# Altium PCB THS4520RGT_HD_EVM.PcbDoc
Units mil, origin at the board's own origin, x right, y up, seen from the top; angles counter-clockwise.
Board outline 1879 x 3030 mil, 4 copper layers (Top Layer L1, MidLayer L2 (GND), MidLayer L3 (Power), Bottom Layer L4), stack 61.2 mil thick; 48 components, 25 nets, 139 pads, 272 vias.
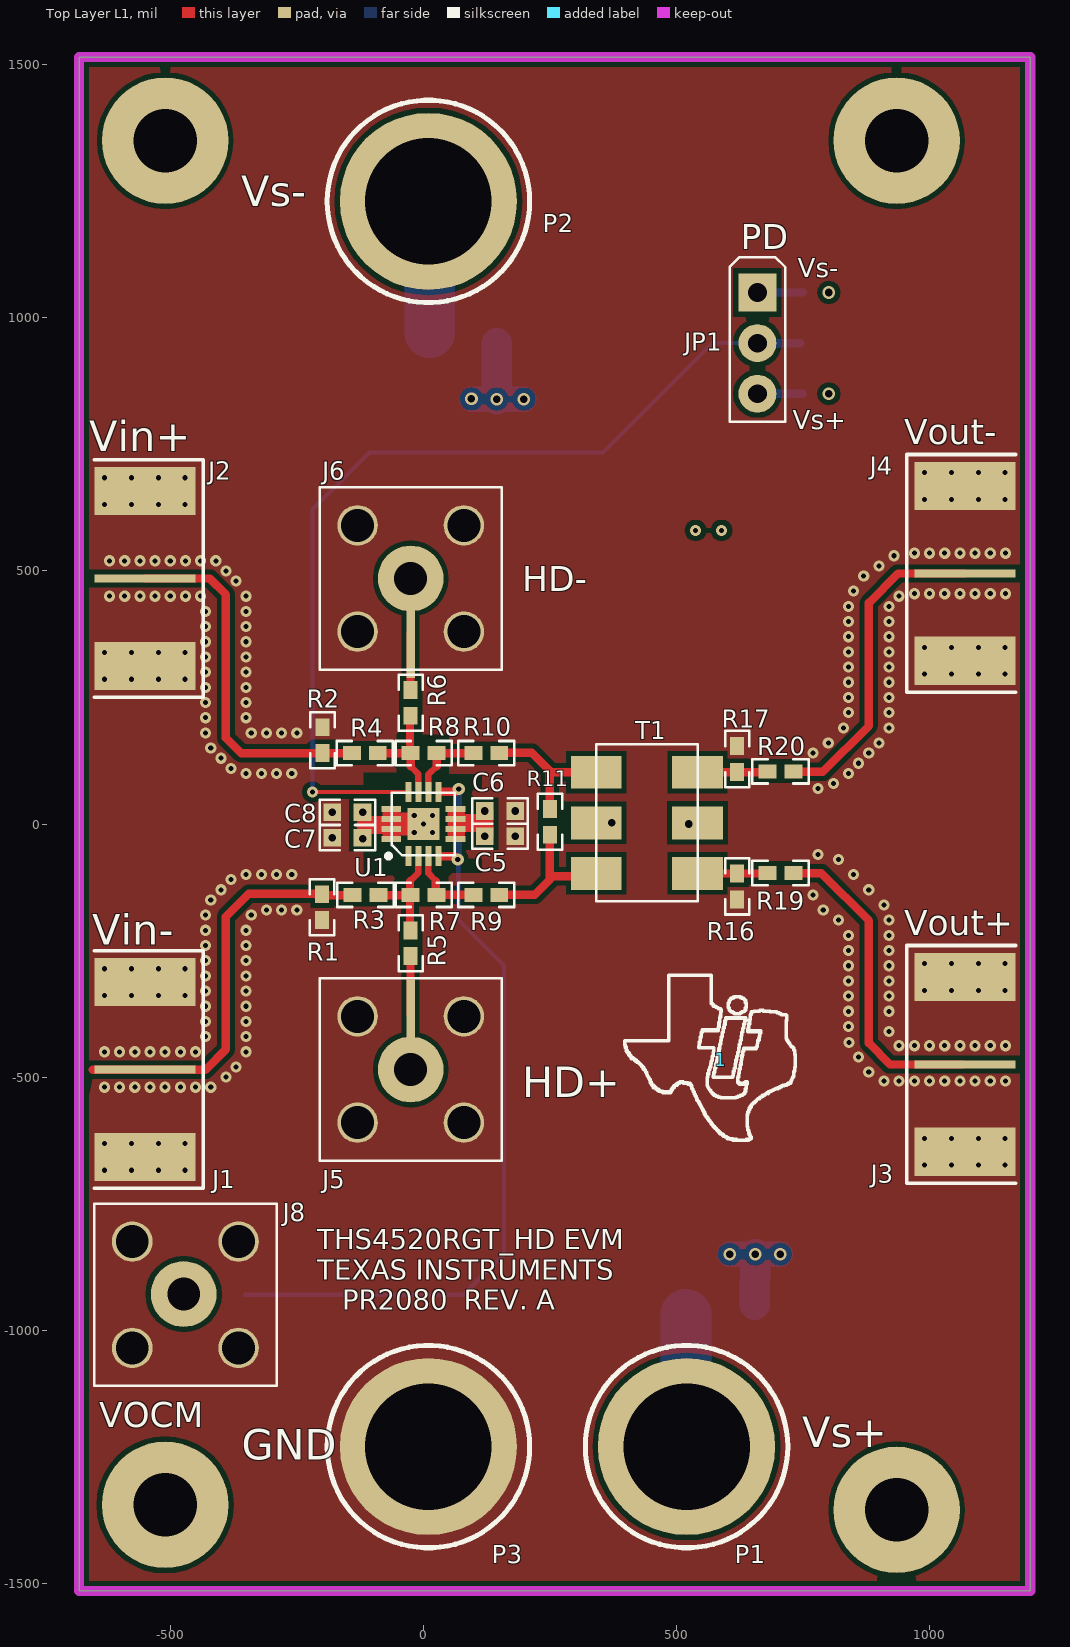
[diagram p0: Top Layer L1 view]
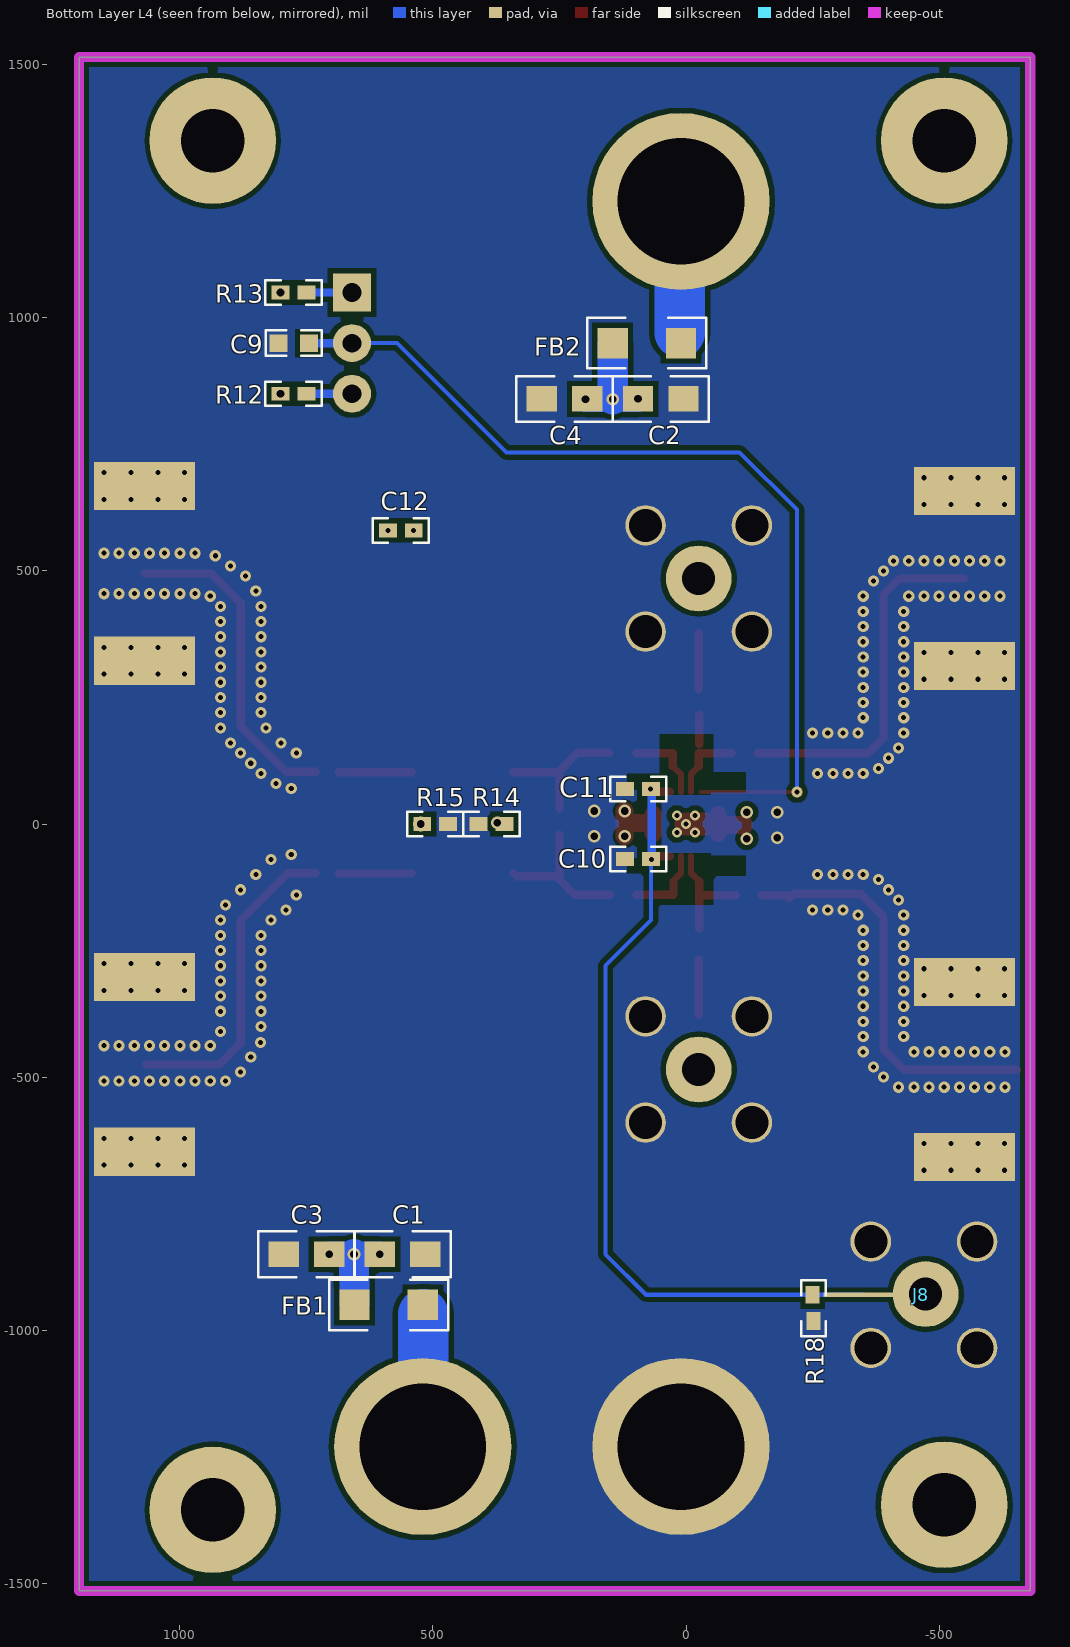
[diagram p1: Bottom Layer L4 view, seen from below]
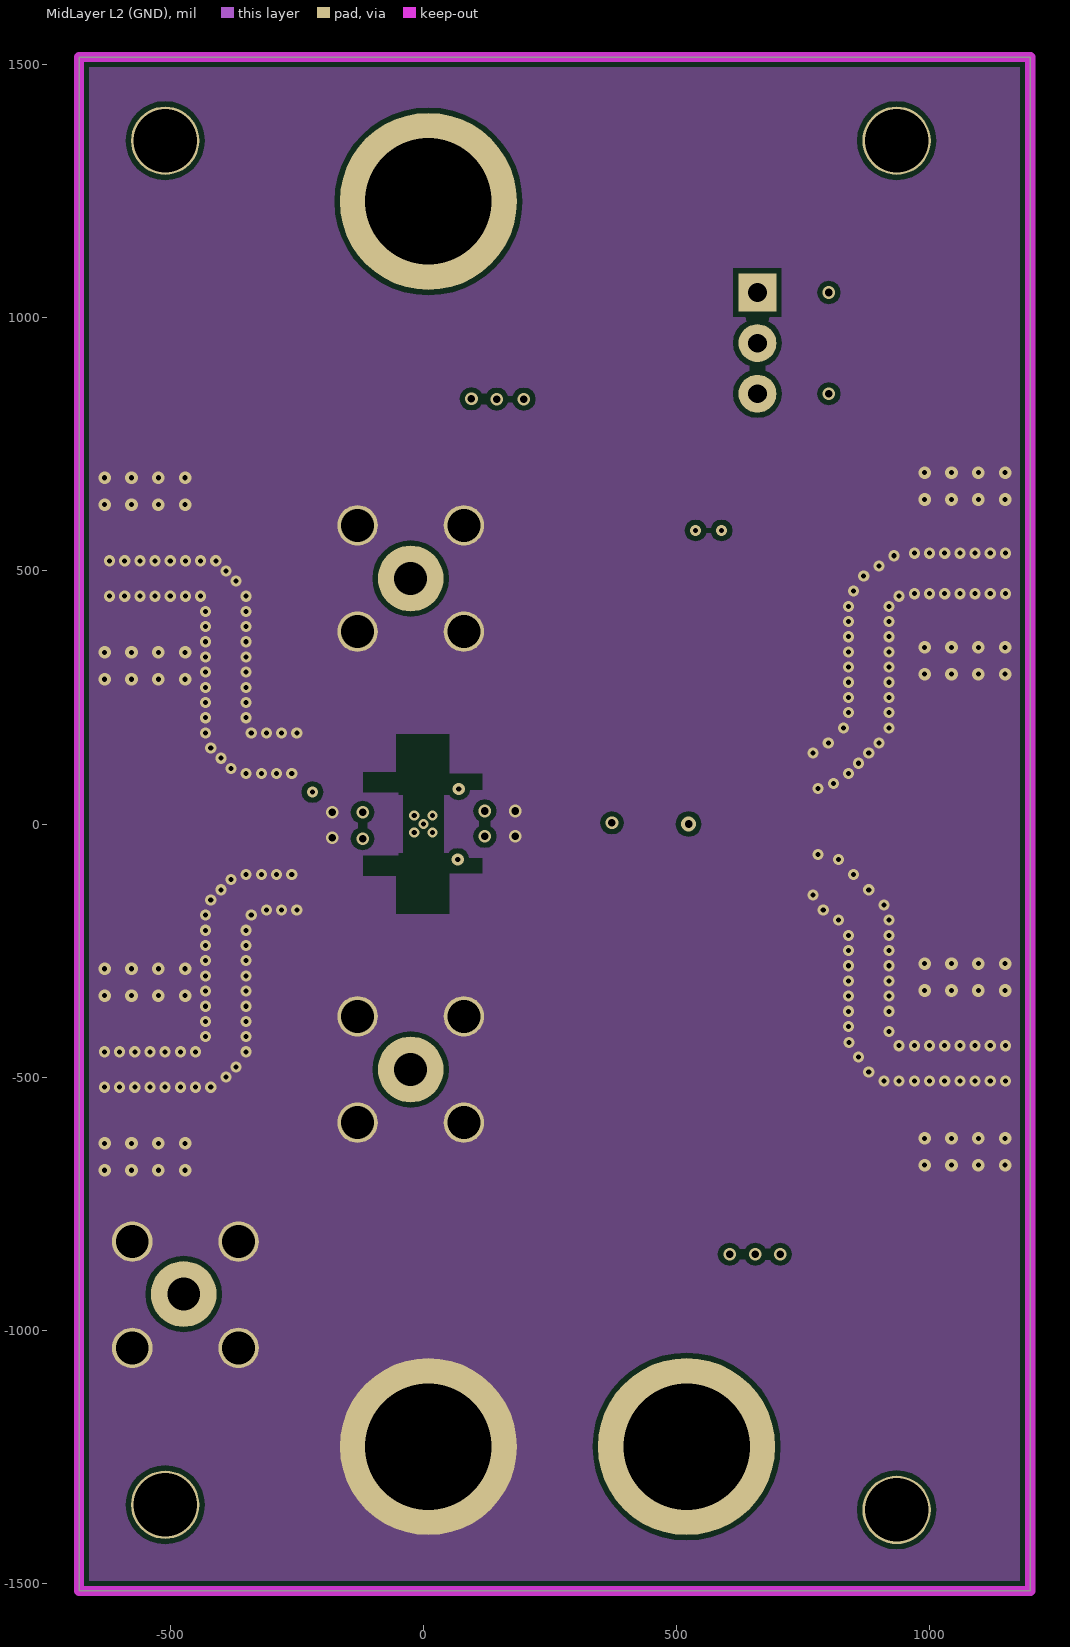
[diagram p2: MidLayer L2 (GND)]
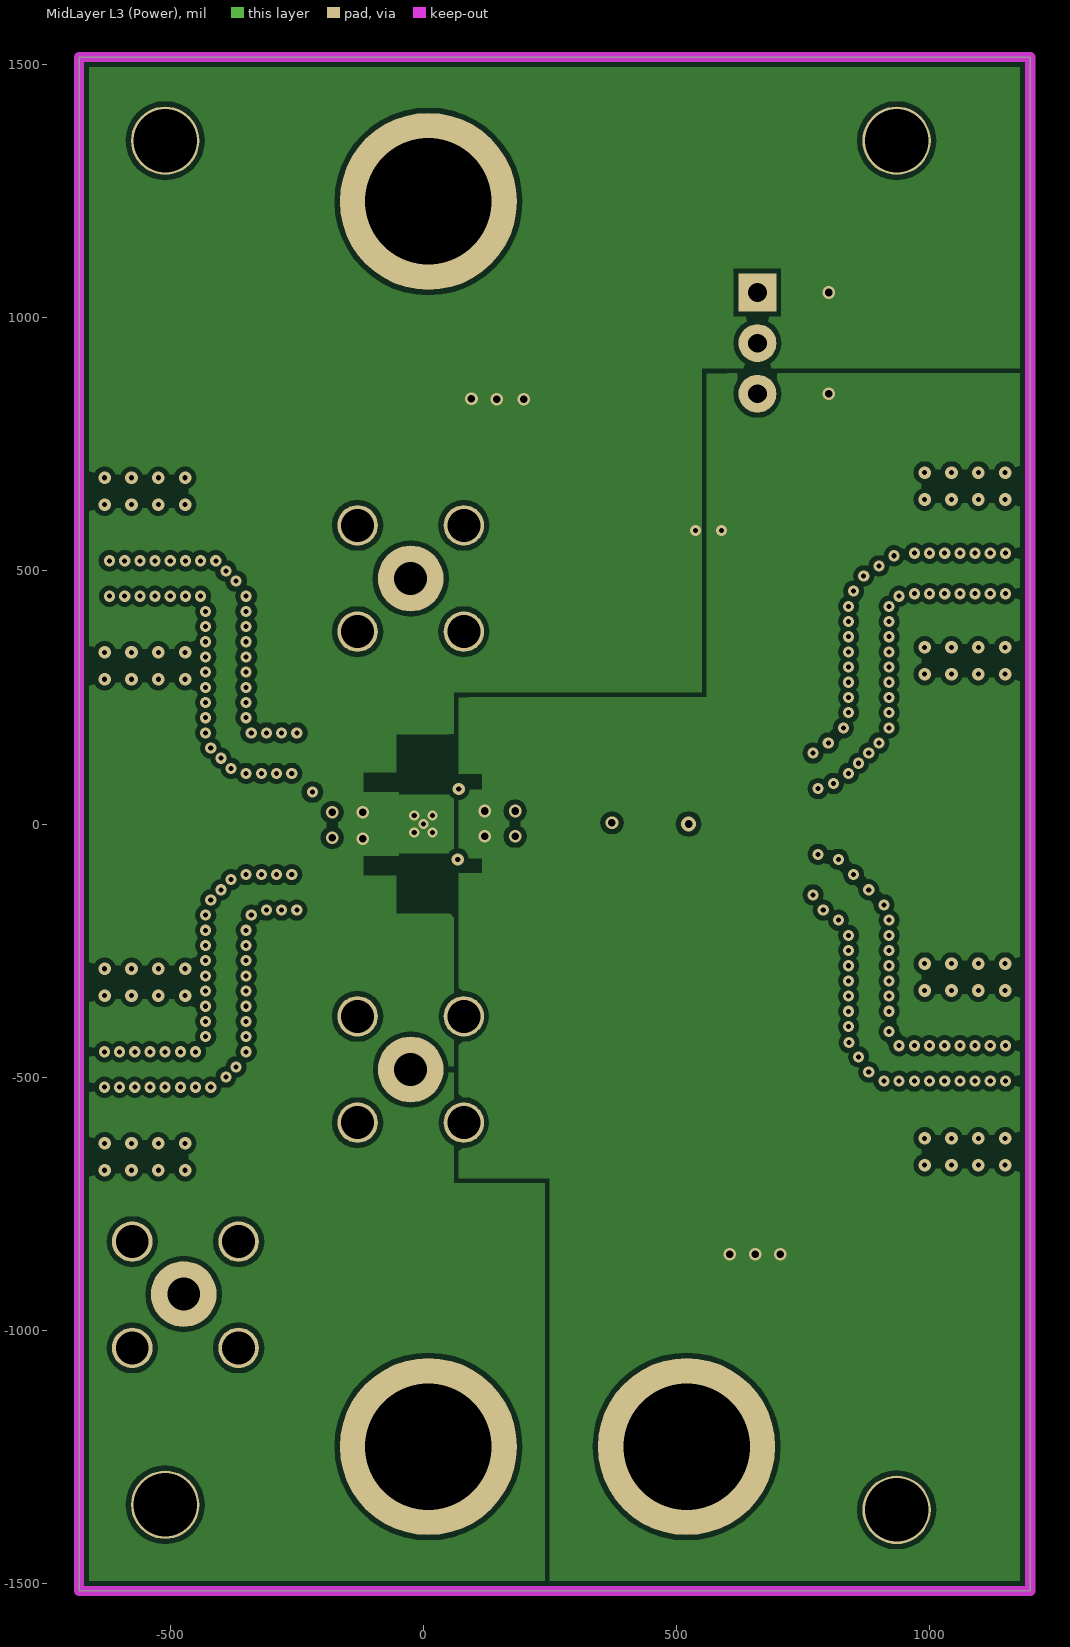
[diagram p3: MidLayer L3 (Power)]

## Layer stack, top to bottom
Top Layer L1: signal copper 1.4
Dielectric: prepreg 10, FR4-STD, Dk 3.66
MidLayer L2 (GND): signal copper 1.4
Dielectric: core 35.6, FR4-STD, Dk 4.8
MidLayer L3 (Power): signal copper 1.4
Dielectric: prepreg 10, FR4-STD, Dk 4.8
Bottom Layer L4: signal copper 1.4

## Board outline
-680,-1515 1199,-1515 1199,1515 -680,1515

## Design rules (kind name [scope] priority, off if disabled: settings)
AcuteAngle [All] p1: minimum=4.50000000000000E+0001 checktracksonly=FALSE
AssemblyTestPointUsage [All] p1: valid=2
Clearance [All] p1: gap=5
ComponentClearance ComponentClearance_ScrewToNut [(HasFootprint('NY PMS 440 0025 PH')) vs (HasFootprint('Keystone_1902C'))] p1: gap=5 collisioncheckmode=3 verticalgap=10 showdistances=FALSE
ComponentClearance ComponentClearance_MountingHoles [InComponentClass('Mounting Holes')] p2: gap=250 collisioncheckmode=3 verticalgap=100000 showdistances=FALSE
ComponentClearance ComponentClearance_SmallPassives [HasFootprint('0201*') or HasFootprint('0402*') or HasFootprint('0508') or HasFootprint('0603*') or HasFootprint('0612') or HasFootprint('0805*') or HasFootprint('0815*') or HasFootprint('0830*') or HasFootprint('1206*') or HasFootprint('1210*') or HasFootprint('1808*') or HasFootprint('1812*') or HasFootprint('1825*') or HasFootprint('2010*') or HasFootprint('2220*') or HasFootprint('2225*') or HasFootprint('2512*') or HasFootprint('2728*') or HasFootprint('3518*') or HasFootprint('3216-18*') or HasFootprint('LEE14A_Copper_Pilar*') or HasFootprint('0306*') vs HasFootprint('0201*') or HasFootprint('0402*') or HasFootprint('0508') or HasFootprint('0603*') or HasFootprint('0612') or HasFootprint('0805*') or HasFootprint('0815*') or HasFootprint('0830*') or HasFootprint('1206*') or HasFootprint('1210*') or HasFootprint('1808*') or HasFootprint('1812*') or HasFootprint('1825*') or HasFootprint('2010*') or HasFootprint('2220*') or HasFootprint('2225*') or HasFootprint('2512*') or HasFootprint('2728*') or HasFootprint('3518*') or HasFootprint('3216-18*') or HasFootprint('LEE14A_Copper_Pilar*') or HasFootprint('0306*')] p3: gap=10 collisioncheckmode=3 verticalgap=10 showdistances=FALSE
ComponentClearance ComponentClearance_THtoSMT [IsThruComponent vs IsSMTComponent] p4: gap=10 collisioncheckmode=3 verticalgap=0 showdistances=FALSE
ComponentClearance ComponentClearance_THtoTH [IsThruComponent vs IsThruComponent] p5: gap=70 collisioncheckmode=3 verticalgap=0 showdistances=FALSE
ComponentClearance [All] p6: gap=40 collisioncheckmode=3 verticalgap=5 showdistances=FALSE
DiffPairsRouting [All] p1: maxlimit=100 minlimit=10 mostfreqgap=10 maxuncoupledlength=1000
FabricationTestPointUsage TestPointUsage [All] p1: valid=2 allowmultiple=FALSE
FabricationTestpoint Testpoint [All] p1: side=3 testpointundercomponent=TRUE minsize=40 maxsize=100 preferedsize=60 minholesize=0 maxholesize=40 preferedholesize=32 testpointgrid=1 allowsidetop=TRUE allowsidebottom=TRUE usegrid=TRUE gridtolerance=0.01
FanoutControl Fanout_LCC [IsLCC] p1: bgadir=Out bgaviamode=Centered fanoutstyle=Auto fanoutdirection=Alternating viagrid=1 // Fanout_LCC (Default Rule)
FanoutControl Fanout_BGA [IsBGA] p2: bgadir=Out bgaviamode=Centered fanoutstyle=Auto fanoutdirection=Alternating viagrid=1 // Fanout_BGA (Default Rule)
FanoutControl Fanout_Default [All] p4: bgadir=Out bgaviamode=Centered fanoutstyle=Auto fanoutdirection=Alternating viagrid=1 // Fanout_Default (Default Rule)
FanoutControl Fanout_Small [(CompPinCount < 5)] p5: bgadir=Out bgaviamode=Centered fanoutstyle=Auto fanoutdirection=OutThenIn viagrid=1 // Fanout_Small (Default Rule)
HoleSize [All] p1: absolutevalues=TRUE maxlimit=251 minlimit=8 maxpercent=80.000 minpercent=20.000
MinimumAnnularRing [All] p1: minimumring=0
MinimumSolderMaskSliver MinimumSolderMaskSliver_Logo [InComponentClass('Logo') vs InComponentClass('Logo')] p1: minsoldermaskwidth=0.7
MinimumSolderMaskSliver [All] p2: minsoldermaskwidth=3.84
PlaneClearance [All] p1: clearance=10
PlaneConnect [All] p1: planeconnectstyle=Direct reliefexpansion=10 reliefentries=4 reliefconductorwidth=10 reliefairgap=10
PolygonConnect [All] p1: connectstyle=Direct reliefconductorwidth=10 reliefentries=4 polygonreliefangle="90 Angle" airgapwidth=10
RoutingVias [All] p1: holewidth=10 width=20 viastyle="Through Hole" minholewidth=8 minwidth=20 maxholewidth=200 maxwidth=360
SilkscreenOverComponentPads [All] p1: minsilkscreentomaskgap=10
SolderMaskExpansion [All] p1: expansion=4
UnConnectedPin [All] p1 off:
Width [All] p1: maxlimit=100 minlimit=8 preferedwidth=16.5 minimp=50.000000 maximp=50.000000 favimp=50.000000 checkconnectedcopper=TRUE
14 further rules are at their usual default settings.

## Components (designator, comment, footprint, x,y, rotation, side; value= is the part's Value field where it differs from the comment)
1 "" TIBUG3 588,-466 r0 top
C1 "10uF" 0805 515,-850 r0 bottom
C2 "10uF" 0805 95,840 r180 bottom
C3 "10uF" 0805 795,-850 r180 bottom
C4 "10uF" 0805 195,840 r0 bottom
C5 "0.1uF" 0603 121.39,-24.32 r0 top
C6 "0.1uF" 0603 181.39,25.68 r180 top
C7 "0.1uF" 0603 -120,-27 r180 top
C8 "0.1uF" 0603 -180,23 r0 top
C9 "0.1uF" 0603 745,950 r0 bottom
C10 "0.1uF" 0402#1 69,-69 r0 bottom
C11 "0.1uF" 0402#1 69,69 r0 bottom
C12 "0.1uF" 0402#1 589.18,580 r180 bottom (schematic designator C11)
FB1 "INDUCTOR" 1206 520,-950 r0 bottom
FB2 "INDUCTOR" 1206 10,950 r0 bottom
J1 "Vin-" "SMA - Surface mount - (Jack end) - w/ edge drawing" -550,-485 r180 top
J2 "Vin+" "SMA - Surface mount - (Jack end) - w/ edge drawing" -550,485 r180 top
J3 "Vo+" "SMA - Surface mount - (Jack end) - w/ edge drawing" 1070,-475 r0 top
J4 "Vo-" "SMA - Surface mount - (Jack end) - w/ edge drawing" 1070,495 r0 top
J5 "HD-" "SMA - COM"#1 -25,-485 r270 top
J6 "HD+" "SMA - COM"#2 -25,485 r90 top
J8 "Vocm" "SMA - COM"#3 -470,-930 r180 top
JP1 "/PD" 3POS_JUMP 660,1050 r270 top
P1 "+2.5V" BANANA_JACK 520,-1230 r90 top
P2 "-2.5V" BANANA_JACK 10,1230 r270 top
P3 "GND" BANANA_JACK 10,-1230 r0 top
R1 "51.1W" 0402#1 -200,-190 r90 top
R2 "51.1W" 0402#1 -199,140 r90 top
R3 "2KW" 0402#1 -140,-140 r0 top
R4 "2KW" 0402#1 -141.18,140 r0 top
R5 "49.9W" 0402#1 -25,-210 r270 top
R6 "49.9W" 0402#1 -25,265 r270 top
R7 "2KW" 0402#1 -25,-140 r0 top
R8 "2KW" 0402#1 -25,140 r0 top
R9 "976W" 0402#1 98.82,-140 r0 top
R10 "976W" 0402#1 98.82,140 r0 top
R11 "56.2W" 0402#1 250,30 r270 top
R12 "10KW" 0402#1 750,850 r0 bottom
R13 "10KW" 0402#1 750,1050 r0 bottom
R14 "49.9W" 0402#1 358.82,0 r0 bottom
R15 "49.9W" 0402#1 470,0 r0 bottom
R16 "49.9W" 0402#1 620,-148.8 r90 top
R17 "49.9W" 0402#1 620,102.61 r90 top
R18 "49.9W" 0402#2 -252,-982.18 r90 bottom
R19 "0W" 0402#1 680,-97 r0 top
R20 "0W" 0402#1 680,104 r0 top
T1 "ADT1-1WT" ADT1-1WT 341.61,102.32 r270 top
U1 "THS4520" "QFN 3X3 (16PIN)" 0,0 r0 top

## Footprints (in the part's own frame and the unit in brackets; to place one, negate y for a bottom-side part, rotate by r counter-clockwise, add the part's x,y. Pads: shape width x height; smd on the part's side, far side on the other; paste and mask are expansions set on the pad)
3POS_JUMP [mil]
  rect 75x75 hole 37: 1(0,0)
  round 75 hole 37: 2(100,0) 3(200,0)
  silkscreen extent -70,-55 255,55
0402#1 [mm]
  rect 0.9x0.7 smd: 1(0,0) 2(1.3,0)
  silkscreen extent -0.76,-0.61 2.06,0.61
0402#2 [mm]
  rect 0.9x0.7 smd: 1(0,0) 2(1.325,0.051)
  silkscreen extent -0.76,-0.61 2.06,0.61
0603 [mil] "0603CS-R15X_LU"
  rect 35x35 smd: 1(0,0) 2(60,0)
  silkscreen extent -25,-25 85,25
0805 [mil]
  rect 60x50 smd: 1(0,0) 2(90,0)
  silkscreen extent -50,-45 140,45
1206 [mil]
  rect 60x60 smd: 1(0,0) 2(135,0)
  silkscreen extent -50,-50 185,50
ADT1-1WT [mm] "SMT RF Transformer"
  rect 1.65x2.54 smd: 1(0,0) 2(2.54,0) 3(5.08,0) 4(5.08,5.08) 5(2.54,5.08) 6(0,5.08)
  silkscreen extent -1.4,0 6.47,5.09
BANANA_JACK [mil]
  round 350 hole 250: 1(0,0)
  silkscreen extent -200,-200 200,200
"QFN 3X3 (16PIN)" [mm]
  rect 0.3x1 smd: 1(-0.75,-1.611) 2(-0.25,-1.611) 3(0.25,-1.611) 4(0.75,-1.611) 9(0.75,1.611) 10(0.25,1.611) 11(-0.25,1.611) 12(-0.75,1.611)
  rect 1x0.3 smd: 5(1.612,-0.75) 6(1.612,-0.25) 7(1.612,0.25) 8(1.612,0.75) 13(-1.611,0.75) 14(-1.611,0.25) 15(-1.611,-0.25) 16(-1.611,-0.75)
  rect 1.6x1.6 smd: 17(0,0)
  silkscreen extent -1.85,-1.71 1.58,1.58
"SMA - COM"#1 [mil]
  round 80 hole 65: 1(-105,105) 1(105,105) 3(-105,-105) 3(105,-105)
  rect 120x16.5 smd: 2(-118.11,0)
  round 130 hole 65: 2(0,0)
  silkscreen extent -180,-180 180,180
"SMA - COM"#2 [mil]
  round 80 hole 65: 1(-105,105) 1(105,105) 3(-105,-105) 3(105,-105)
  rect 157.48x16.5 smd: 2(-118.11,0)
  round 130 hole 65: 2(0,0)
  silkscreen extent -180,-180 180,180
"SMA - COM"#3 [mil]
  round 80 hole 65: 1(-105,105) 1(105,105) 3(-105,-105) 3(105,-105)
  rect 160x8 smd far side: 2(-118.11,0)
  round 130 hole 65: 2(3.39,-1.32)
  silkscreen extent -180,-180 180,180
"SMA - Surface mount - (Jack end) - w/ edge drawing" [mil]
  rect 200x16.5 smd: 1(0,0)
  rect 200x95 smd: 2(0,172.5) 3(0,-172.5)
  rect 200x95 smd far side: 4(0,-172.5) 5(0,172.5)
  silkscreen extent -115,-235 100,235, body extent -95,-190 487,190, height 155
TIBUG3 [mil]
  silkscreen extent -190,-159 147,167

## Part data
1: "Pattern, TI Bug 0.3\" High"
C1 C2 C3 C4: library part "CAP (SM)", "CAP CER 10UF 50V 10% X5R 1206"
C5 C6 C7 C8 C9 C10 C11 C12: library part "CAP (SM)", "CAP CER 0.1UF 16V 5% X7R 0402"
FB1 FB2: "FERRITE BEAD 90 OHM 1206"
J1 J2 J3 J4: library part "SMA (END Launch)", "Connector, SMT, End launch SMA 50 ohm"
J5 J6 J8: library part "SMA JACK"
JP1: library part JUMP_3
P1 P2 P3: library part "TEST POINT"
R1 R2 R3 R4 R7 R8: library part "RES (SM)"
R5 R6: library part "RES (SM)", "RES SMD 49.9 OHM 1% 1/4W 1206"
R9 R10: library part "RES (SM)", "RES SMD 976 OHM 1% 1/16W 0402"
R11: library part "RES (SM)", "RES SMD 56.2 OHM 1% 1/16W 0402"
R12 R13: library part "RES (SM)", "RES SMD 10K OHM 1% 1/16W 0402"
R14 R15 R16 R17 R18: library part "RES (SM)", "RES SMD 49.9 OHM 1% 1/16W 0402"
R19 R20: library part "RES (SM)", "RES SMD 0.0 OHM JUMPER 1/16W"
U1: library part THS4520_RGT

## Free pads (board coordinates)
  round 250 / inner round 135 / far side round 250 hole 125: 0(-510,-1345) 0(-510,1350) 0(935,-1355) 0(935,1350)

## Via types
v1: diameter 22, hole 10, Top Layer L1 to Bottom Layer L4, 183 vias
v2: diameter 25, hole 10, Top Layer L1 to Bottom Layer L4, 64 vias
v3: diameter 25, hole 15, Top Layer L1 to Bottom Layer L4, 17 vias
v4: diameter 20, hole 10, Top Layer L1 to Bottom Layer L4, 5 vias
v5: diameter 24, hole 10, Top Layer L1 to Bottom Layer L4, 2 vias
v6: diameter 30, hole 15, Top Layer L1 to Bottom Layer L4, 1 vias

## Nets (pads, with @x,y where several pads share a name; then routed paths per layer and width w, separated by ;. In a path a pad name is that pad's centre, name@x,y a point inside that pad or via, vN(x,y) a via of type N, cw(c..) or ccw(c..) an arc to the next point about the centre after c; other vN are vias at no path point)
+2.5V: FB1.1 P1.1 | length 264.7
  Bottom Layer L4 w100: P1.1@519,-1233 FB1.1@519,-968.32
+VS: C1.2 C3.2 C5.1 C6.2 C12.1 FB1.2 R12.2 U1.5 U1.6 U1.7 U1.8 | length 338.4
  Top Layer L1 w35: 65,-18 65,18 ; 69,2 121.39,2 ; v3(121.39,-24.32) 121.39,2 ; v3(121.39,25.68) 121.39,2
  Bottom Layer L4 w50: v3(605,-850) v3(656,-850) v3(705,-850)
  Bottom Layer L4 w60: FB1.2 v3(656,-850)
  other v1: 589.18,580
  other v3: 801.18,850
-2.5V: FB2.1 P2.1 | length 283
  Bottom Layer L4 w100: FB2.1@12.61,970.32 P2.1@12.61,1253.32
-VS: C2.1 C4.1 C7.1 C8.2 C12.2 FB2.2 R13.2 U1.13 U1.14 U1.15 U1.16 U1.17 | length 348.3
  Top Layer L1 w35: -115,-2 -79,-2 ; -63.44,-18 U1.15 U1.14 -63.44,18
  Top Layer L1 w45: -62,0 v4(0,0)
  Bottom Layer L4 w50: C2.1@95,839.32 v3(145,839.32) v3(198.61,839.32)
  Bottom Layer L4 w60: v3(145,839.32) FB2.2
  other v1: 538,580
  other v3: -120,-29 -120,23 95,840 801.18,1050
  other v4: -18,-17 18,-17 -18,17 18,17
/PD: C9.1 JP1.2 U1.12 | length 1844.3
  Top Layer L1 w8: v1(-219,63) U1.12@-30,63
  Bottom Layer L4 w8: v1(-219,63) -219,621 -106,734 355,734 571,950 JP1.2@657,950
  Bottom Layer L4 w16.5: JP1.2 C9.1
GND: C1.1 C2.2 C3.1 C4.2 C5.2 C6.1 C7.2 C8.1 C9.2 C10.2 C11.2 J1.2 J1.3 J1.4 J1.5 J2.2 J2.3 J2.4 J2.5 J3.2 J3.3 J3.4 J3.5 J4.2 J4.3 J4.4 J4.5 J5.1 J5.3 J6.1 J6.3 J8.1 J8.3 P3.1 R1.1 R2.2 R14.2 R15.1 R16.1 R17.2 R18.1
  other v1: -630,-520 -600,-520 -570,-520 -540,-520 -510,-520 -480,-520 -450,-520 -420,-520 910,-508 940,-508 970,-508 1000,-508 1030,-508 1060,-508 1090,-508 1120,-508 1150,-508 -390,-500 880,-490 -370,-480 860,-460 -630,-450 -600,-450 -570,-450 -540,-450 -510,-450 -480,-450 -450,-450 -350,-450 940,-438 970,-438 1000,-438 1030,-438 1060,-438 1090,-438 1120,-438 1150,-438 841,-432 -430,-420 -350,-420 920,-410 840,-400 -430,-390 -350,-390 840,-370 920,-370 -430,-360 -350,-360 840,-340 920,-340 -430,-330 -350,-330 840,-310 920,-310 -430,-300 -350,-300 840,-280 920,-280 -430,-270 -350,-270 840,-250 920,-250 -430,-240 -350,-240 840,-220 920,-220 -430,-210 -350,-210 820,-190 920,-190 -430,-180 -340,-180 -310,-170 -280,-170 -250,-170 790,-170 910,-160 -420,-150 770,-140 -400,-130 880,-130 -380,-110 -350,-100 -320,-100 -290,-100 -260,-100 850,-100 820,-70 780,-60 780,70 810,80 -350,100 -320,100 -290,100 -260,100 840,100 -380,110 860,120 -400,130 770,140 880,140 -420,150 800,160 900,160 -430,180 -340,180 -310,180 -280,180 -250,180 830,190 920,190 -430,210 -350,210 840,220 920,220 -430,240 -350,240 840,250 920,250 -430,270 -350,270 840,280 920,280 -430,300 -350,300 840,310 920,310 -430,330 -350,330 840,340 920,340 -430,360 -350,360 840,370 920,370 -430,390 -350,390 840,400 920,400 -430,420 -350,420 840,430 920,430 -620,450 -590,450 -560,450 -530,450 -500,450 -470,450 -440,450 -350,450 940,450 970,455 1000,455 1030,455 1060,455 1090,455 1120,455 1150,455 850,460 -370,480 870,490 -390,500 900,510 -620,520 -590,520 -560,520 -530,520 -500,520 -470,520 -440,520 -410,520 930,530 970,535 1000,535 1030,535 1060,535 1090,535 1120,535 1150,535
  other v2: -629.5,-684 -576.5,-684 -523.5,-684 -470.5,-684 990.5,-674 1043.5,-674 1096.5,-674 1149.5,-674 -629.5,-631 -576.5,-631 -523.5,-631 -470.5,-631 990.5,-621 1043.5,-621 1096.5,-621 1149.5,-621 -629.5,-339 -576.5,-339 -523.5,-339 -470.5,-339 990.5,-329 1043.5,-329 1096.5,-329 1149.5,-329 -629.5,-286 -576.5,-286 -523.5,-286 -470.5,-286 990.5,-276 1043.5,-276 1096.5,-276 1149.5,-276 -629.5,286 -576.5,286 -523.5,286 -470.5,286 990.5,296 1043.5,296 1096.5,296 1149.5,296 -629.5,339 -576.5,339 -523.5,339 -470.5,339 990.5,349 1043.5,349 1096.5,349 1149.5,349 -629.5,631 -576.5,631 -523.5,631 -470.5,631 990.5,641 1043.5,641 1096.5,641 1149.5,641 -629.5,684 -576.5,684 -523.5,684 -470.5,684 990.5,694 1043.5,694 1096.5,694 1149.5,694
  other v3: -180,-27 181.39,-24.32 -180,23 181.39,25.68
NetJ1_1: J1.1 R1.2 R3.1 | length 800.8
  Top Layer L1 w16.5: -653.39,-485.68 -430.68,-485.68 -390,-445 -390,-183 -378.75,-171.75 -356.25,-149.25 -345,-138 -211.82,-138 R1.2@-203,-146.82 ; R1.2@-199,-141 R3.1@-149.68,-140.82
NetJ2_1: J2.1 R2.1 R4.1 | length 717.5
  Top Layer L1 w16.5: J2.1 -422,485 -390,453 -390,170 -360,140 R2.1 R4.1
NetJ3_1: J3.1 R19.2 | length 633.9
  Top Layer L1 w16.5: R19.2 786,-97 880,-191 880,-433 922,-475 J3.1@1066.77,-475
NetJ4_1: J4.1 R20.2 | length 643.7
  Top Layer L1 w16.5: R20.2@731,103 789,103 880,194 880,437 938,495 J4.1
NetJ5_2: J5.2 R5.2 | length 109
  Top Layer L1 w16.5: J5.2@-25.39,-376.68 R5.2@-25.39,-267.68
NetJ6_2: J6.2 R6.1 | length 111
  Top Layer L1 w16.5: R6.1@-25.39,266.32 J6.2@-25.39,377.32
NetJP1_1: JP1.1 R13.1 | length 90
  Bottom Layer L4 w16.5: JP1.1 R13.1
NetJP1_3: JP1.3 R12.1 | length 90
  Bottom Layer L4 w16.5: JP1.3 R12.1
NetR3_2: R3.2 R5.1 R7.1 U1.2 | length 221.8
  Top Layer L1 w12.5: -26.39,-113.39 -9.84,-96.84 U1.2
  Top Layer L1 w16.5: R3.2@-98.32,-141 R7.1@-26.39,-141 ; R5.1@-26.39,-206.5 -26.39,-147.68 -26.39,-113.39
NetR4_2: R4.2 R6.2 R8.1 U1.11 | length 206.7
  Top Layer L1 w12.5: -25,114 -9.84,98.84 U1.11
  Top Layer L1 w16.5: R4.2 R8.1 -25,114 ; -26.39,157.32 R6.2@-26.39,216.14
NetR7_2: R7.2 R9.1 U1.3 | length 155.4
  Top Layer L1 w12.5: U1.3 9.84,-96.84 24.8,-111.8 24.8,-113
  Top Layer L1 w16.5: R7.2@24.8,-140 24.8,-113 ; R7.2 R9.1
NetR8_2: R8.2 R10.1 U1.10 | length 156
  Top Layer L1 w12.5: U1.10 9.84,97.84 26.18,114.18
  Top Layer L1 w16.5: 26.18,114.18 R8.2 R10.1
NetR9_2: R9.2 R11.2 T1.3 | length 294.7
  Top Layer L1 w16.5: R9.2 220,-140 250,-110 R11.2 ; 250,-103 334.94,-103 T1.3@340.94,-97
NetR10_2: R10.2 R11.1 T1.1 | length 278.8
  Top Layer L1 w16.5: R10.2@152,141 214,141 250,105 R11.1 ; 250.68,102.32 T1.1
NetR14_1: R14.1 T1.2
  other v3: 372.61,2.32
NetR15_2: R15.2 T1.5
  other v6: 524,0
NetR16_2: R16.2 R19.1 T1.4 | length 145
  Top Layer L1 w16.5: T1.4 R19.1@686.61,-97.68
NetR17_1: R17.1 R20.1 T1.6 | length 145
  Top Layer L1 w16.5: T1.6 R20.1@686.61,102.32
VOCM: C10.1 C11.1 J8.2 R18.2 U1.4 U1.9 | length 1580.5
  Top Layer L1 w16.5: U1.4@32,-63.44 61.44,-63.44 v5(68,-70) ; U1.9@32,63.44 63.44,63.44 v5@69,69
  Bottom Layer L4 w8: J8.2@-351.89,-930 79,-930 159,-850 159,-280 69,-190 C10.1
  Bottom Layer L4 w16.5: v5(68,-70) 68,67.32 v5(70,69.32)
pads on no net: U1.1

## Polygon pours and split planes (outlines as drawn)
GND on Bottom Layer L4 "Bottom Layer" (solid, pour order 8): -680,-1515 1199,-1515 1199,1537.43 -680,1537.43 -680,-1515
GND on MidLayer L2 (GND) "Mid Layer 1" (solid, pour order 6): -680,-1515 1199,-1515 1199,1494.61 -680,1494.61 -680,-1515
GND on Top Layer L1 "Top Layer" (solid, pour order 5): -680,-1515 1199,-1515 1199,1537.43 -680,1537.43 -680,-1515
+VS on MidLayer L3 (Power) "Top Layer" (solid, pour order 13): 250,-1515 1199,-1515 1199,-1466 1199,890 1016,890 560,890 560,250 334,250 70,250 70,-700 250,-700 250,-1515
-VS on MidLayer L3 (Power) "Top Layer" (solid, pour order 15): 240,-1515 -680,-1515 -680,-1481 -680,1515 -569,1515 1199,1515 1199,900 1110,900 550,900 550,852 550,260 511,260 70,260 60,260 60,-260 60,-710 240,-710 240,-1515

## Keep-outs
Keep-Out Layer:
  the board outline again, w20
  text ".Layer_Name" at -222.39,-2376.17 h60

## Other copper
Top Layer L1:
  pour cut-out: -118.39,102.32 -53.39,102.32 -53.39,177.32 51.61,177.32 51.61,99.32 116.61,99.32 116.61,67.32 51.61,67.32 51.61,57.32 -48.39,57.32 -48.39,62.32 -118.39,62.32
  pour cut-out: 116.61,-97.68 50,-97 50,-160 -54,-160 -53.39,-102.68 -118.39,-102.68 -118.39,-62.68 -48.39,-62.68 -48.39,-57.68 51.61,-57.68 51.61,-67.68 116.61,-67.68
  text ".Layer_Name" at -222.39,-2376.17 h60
MidLayer L2 (GND):
  pour cut-out: -40,90 -40,-90 40,-90 40,90
  pour cut-out: -118.39,102.32 -53.39,102.32 -53.39,177.32 51.61,177.32 51.61,99.32 116.61,99.32 116.61,67.32 51.61,67.32 51.61,57.32 -48.39,57.32 -48.39,62.32 -118.39,62.32
  pour cut-out: 116.61,-97.68 51.61,-97.68 51.61,-177.68 -53.39,-177.68 -53.39,-102.68 -118.39,-102.68 -118.39,-62.68 -48.39,-62.68 -48.39,-57.68 51.61,-57.68 51.61,-67.68 116.61,-67.68
MidLayer L3 (Power):
  pour cut-out: -118.39,102.32 -53.39,102.32 -53.39,177.32 51.61,177.32 51.61,99.32 116.61,99.32 116.61,67.32 51.61,67.32 51.61,57.32 -48.39,57.32 -48.39,62.32 -118.39,62.32
  pour cut-out: 116.61,-97.68 51.61,-97.68 51.61,-177.68 -53.39,-177.68 -53.39,-102.68 -118.39,-102.68 -118.39,-62.68 -48.39,-62.68 -48.39,-57.68 51.61,-57.68 51.61,-67.68 116.61,-67.68
Bottom Layer L4:
  pour cut-out: -118.39,102.32 -53.39,102.32 -53.39,177.32 51.61,177.32 51.61,99.32 116.61,99.32 116.61,67.32 51.61,67.32 51.61,57.32 -48.39,57.32 -48.39,62.32 -118.39,62.32
  pour cut-out: 116.61,-97.68 50,-97 50,-160 -54,-160 -53.39,-102.68 -118.39,-102.68 -118.39,-62.68 -48.39,-62.68 -48.39,-57.68 51.61,-57.68 51.61,-67.68 116.61,-67.68
  text ".Layer_Name" at -222.39,-2376.17 h60

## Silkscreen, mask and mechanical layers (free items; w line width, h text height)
Top Overlay:
  text "Vs-" at -360,1220 h60
  text "PD" at 627,1135 h50
  text "Vs-" at 740,1080 h37.5
  text "Vs+" at 730,780 h37.5
  text "Vout-" at 950,750 h50
  text "Vin+" at -660,736 h60
  text "HD-" at 195,460 h50
  text "Vout+" at 950,-220 h50
  text "Vin-" at -654,-239 h60
  text "HD+" at 195,-540 h60
  text "THS4520RGT_HD EVM" at -210,-840 h40
  text "TEXAS INSTRUMENTS" at -210,-900 h40
  text "PR2080" at -160,-960 h40
  text "REV. A" at 80,-960 h40
  text "VOCM" at -640,-1192 h50
  text "Vs+" at 749,-1231 h60
  text "GND" at -359,-1256 h60
  text ".Layer_Name" at -222.39,-2376.17 h60
Bottom Overlay:
  text ".Layer_Name" at -222.39,-2376.17 h60
Top Paste:
  text ".Layer_Name" at -222.39,-2376.17 h60
Bottom Paste:
  text ".Layer_Name" at -222.39,-2376.17 h60
Top Solder:
  text ".Layer_Name" at -222.39,-2376.17 h60
  text ".Layer_Name" at -222.39,-2376.17 h60
Bottom Solder:
  text ".Layer_Name" at -222.39,-2376.17 h60
Drill Guide:
  text ".Layer_Name" at -222.39,-2376.17 h60
M1 Board Outline:
  text ".Layer_Name" at -222.39,-2376.17 h60
M2 Board Dimensions:
  rectangle: -674.89,-1928.18 -299.89,-1803.18
  rectangle: -799.89,-1803.18 -674.89,-1678.18
  lines w7: -799.89,-1803.18 200.11,-1803.18 ; -674.89,-1928.18 -674.89,-1678.18 ; -549.89,-1928.18 -549.89,-1678.18 ; -299.89,-1928.18 -299.89,-1678.18 ; -49.89,-1928.18 -49.89,-1678.18 ; -799.89,-1928.18 -799.89,-1678.18 200.11,-1678.18 200.11,-1928.18 -799.89,-1928.18
  lines w10: -820,-1455 -800,-1515 ; -820,1460 -800,1520 ; -810,-1515 -790,-1515 ; -810,1520 -790,1520 ; -800,-278.41 -800,-1515 ; -800,283.41 -800,1520 ; -798.39,-1977.68 -798.39,-1957.68 ; -780,-1455 -800,-1515 ; -780,1460 -800,1520 ; -740,-425 -720,-485 ; -740,425 -720,485 ; -738.39,-1987.68 -798.39,-1967.68 ; -738.39,-1947.68 -798.39,-1967.68 ; -730,-485 -710,-485 ; -730,485 -710,485 ; -720,-250.92 -720,-485 ; -720,250.92 -720,485 ; -700,-425 -720,-485 ; -700,425 -720,485 ; -680,-1625 -680,-1605 ; -620,-1635 -680,-1615 ; -620,-1595 -680,-1615 ; -574.3,-1967.68 -798.39,-1967.68 ; -22.47,-1967.68 201.61,-1967.68 ; -16.42,-1615 -680,-1615 ; 141.61,-1987.68 201.61,-1967.68 ; 141.61,-1947.68 201.61,-1967.68 ; 201.61,-1977.68 201.61,-1957.68 ; 535.42,-1615 1199,-1615 ; 1139,-1635 1199,-1615 ; 1139,-1595 1199,-1615 ; 1199,-1625 1199,-1605 ; 1231,-418.08 1251,-478.08 ; 1231,431.92 1251,491.92 ; 1241,-478.08 1261,-478.08 ; 1241,491.92 1261,491.92 ; 1251,-244 1251,-478.08 ; 1251,257.85 1251,491.92 ; 1271,-418.08 1251,-478.08 ; 1271,431.92 1251,491.92
  text "970 (mil)" at 1286.99,-234 h60 r90
  text "970 (mil)" at -684.01,-240.92 h60 r90
  text "3035 (mil)" at -764.01,-268.41 h60 r90
  text "1879 (mil)" at -6.42,-1650.99 h60
  text "1000 (mil)" at -564.3,-2003.67 h60
  text ".Layer_Name" at -222.39,-2376.17 h60
M4 3D STEP Bottom:
  text ".Layer_Name" at -222.39,-2376.17 h60
M5 Assembly Top:
  lines w10: -1091.39,-2447.84 5508.61,-2447.84 ; -1091.39,-2244.51 5510.61,-2244.51 ; -1091.39,-2041.18 -1091.39,-2651.18 2913.61,-2651.18 5510.61,-2651.18 5510.61,-2041.18 -1090.89,-2041.18 -1090.89,-2651.18 484.61,-2651.18 ; 1373.61,-2651.18 1373.61,-2041.18 ; 2640.61,-2244.51 2640.61,-2041.18 ; 3480.61,-2244.51 3480.61,-2041.18 ; 4102.61,-2657.68 4102.61,-2454.84
  text "COMPONENTS MARKED 'DNP' SHOULD NOT BE POPULATED." at 354.11,-1836.18 h60
  text "ASSEMBLY VARIANT:" at 353.61,-1951.68 h60
  text ".VariantName" at 1389.61,-1951.68 h60
  text "PCB VIEWED FROM TOP SIDE" at -1027.89,-2173.34 h60
  text "BOARD#:" at 1448.61,-2173.34 h60
  text "THS4520RGT_HD_EVM" at 1850,-2173.34 h60
  text "REV: A" at 2838.61,-2173.34 h60
  text "Rev. A" at 3676.61,-2173.34 h60
  text ".VersionControl_RevNumber" at 4182.61,-2173.34 h60
  text "IGNORE ->" at -1027.89,-2376.17 h60
  text "PLOT NAME =" at -1027.89,-2582.01 h60
  text "THS4520RGT_HD_EVM" at -222.39,-2582.01 h60
  text "GENERATED    :" at 1450.61,-2582.01 h60
  text ".Print_Date" at 2320.11,-2582.01 h60
  text ".Print_Time" at 3049.11,-2582.01 h60
  text "TEXAS INSTRUMENTS" at 4313.61,-2582.01 h60
M9 Title Sheet:
  drawing of 57 lines, arcs and shapes, not listed
  text "1" at -59.55,6518.82 h70
  text "2" at 2436.11,6518.82 h70
  text "3" at 4925.46,6518.82 h70
  text "4" at 7432.12,6518.82 h70
  text "5" at 9931.11,6518.82 h70
  text "6" at 12436.11,6518.82 h70
  text "A" at -1215.89,5375.82 h70
  text "A" at 13584.11,5375.82 h70
  text "B" at -1215.89,2995.82 h70
  text "B" at 13584.11,2995.82 h70
  text "C" at -1215.89,620.82 h70
  text "C" at 13584.11,620.82 h70
  text "PROJECT TITLE:" at 10544.11,-1240.18 h45
  text "THS4520RGT_HD_EVM.PRJPCB" at 10594.11,-1373.5 h70
  text "DESIGNED FOR:" at 10544.11,-1541.18 h45
  text ".PRJ_Customer" at 10594.11,-1681.18 h70
  text "D" at -1215.89,-1749.18 h70
  text "D" at 13584.11,-1749.18 h70
  text "FILE NAME:" at 10544.11,-1841.18 h45
  text "THS4520RGT_HD_EVM" at 10594.11,-1961.18 h70
  text "Texas Instruments (TI) and/or its licensors do not warrant the accuracy or completeness of this specification" at 5574.61,-2123.02 h45
  text "ENGINEER:" at 10544.11,-2131.18 h45
  text "LAYOUT BY:" at 12049.11,-2131.18 h45
  text "or any information contained therein. TI and/or its licensors do not warrant that this design will meet" at 5529.63,-2235.68 h45
  text "Samir Cherian" at 10594.11,-2286.17 h70
  text "Phung Luong" at 12099.61,-2286.17 h70
  text "the specifications, will be suitable for your application or fit for any particular purpose, or will operate in" at 5529.63,-2348.35 h45
  text ".Layer_Name" at -222.39,-2376.17 h60
  text "ALTIUM DESIGNER VERSION:" at 12049.11,-2441.18 h45
  text "an implementation. TI and/or its licensors do not warrant that the design is production worthy. You should" at 5529.63,-2461.01 h45
  text "completely validate and test your design implementation to confirm the system functionality for your application." at 5574.61,-2573.68 h45
  text ".print_Scale" at 10594.11,-2574.5 h70
  text "PR2080" at 12099.61,-2574.5 h70
  text "1" at -59.55,-2781.18 h70
  text "2" at 2436.11,-2781.18 h70
  text "3" at 4925.46,-2781.18 h70
  text "4" at 7432.12,-2781.18 h70
  text "5" at 9931.11,-2781.18 h70
  text "6" at 12436.11,-2781.18 h70
M10 Fab Notes:
  drawing of 212 lines, arcs and shapes, not listed
  text "DESIGN INFORMATION" at 11581.63,5292.32 h60
  text "(REFER ALSO ARRAY/PANEL PROFILING INFORMATION)" at 11220.07,5130.61 h60
  text "BOARD SIZE" at 10534.07,5126.32 h60
  text "1879 MIL" at 10996.39,4998.5 h60
  text "X" at 11502.07,4998.5 h60
  text "3035 MIL" at 11733.39,4998.5 h60
  text "Number of Layers :" at 10937.07,4801.32 h60
  text "4" at 12031.89,4791.32 h60
  text "MIN. TRACK WIDTH:" at 10937.07,4662.32 h60
  text "8" at 12033.32,4662.33 h60
  text "MIL" at 12188.07,4662.32 h60
  text "MIN. CLEARANCE:" at 10937.07,4530.32 h60
  text "5" at 12033.32,4530.33 h60
  text "MIL" at 12188.07,4530.32 h60
  text "MIN. VIA PAD SIZE:" at 10937.07,4398.32 h60
  text "100" at 12003.33,4398.33 h60
  text "MIL" at 12188.07,4398.32 h60
  text "0.05mm (2MIL)" at 11632.07,4256.61 h60
  text "MINIMUM ANNULAR RING" at 10607.84,4252.33 h60
  text "EXTERNAL" at 12340.07,4252.33 h60
  text "PER" at 10807.84,4134.33 h60
  text "IPC-D-275 CLASS 2 LEVEL C" at 11027.84,4134.32 h60
  text "MIL, HOLES" at 12516.07,4022.04 h60
  text "+/-" at 12123.61,4021.32 h60
  text "+/-" at 12977.61,4021.32 h60
  text "REGISTRATION TOLERANCES:" at 10607.84,4016.32 h60
  text "METAL" at 11807.61,4016.32 h60
  text "5" at 12383.82,4016.33 h60
  text "3" at 13216.82,4016.33 h60
  text "MIL" at 13333.07,4016.32 h60
  text "MATERIAL:" at 10533.07,3806.87 h60
  text "FR-4 High Tg" at 11519.52,3666.53 h60
  text "FR-408" at 10954.08,3657.96 h60
  text "X" at 12255.07,3658.32 h60
  text "FR4-STD" at 12442.07,3657.96 h60
  text "OTHER" at 12442.07,3657.96 h60
  text "62 MIL (1.6mm) +/-10%" at 11274.18,3495.25 h60
  text "THICKNESS:" at 10607.84,3490.96 h60
  text "X" at 11146.01,3490.96 h60
  text "OTHER" at 12559.07,3490.96 h60
  text "TOLERANCE:" at 10607.84,3332.96 h60
  text "X" at 11447.15,3332.96 h60
  text "ANSI IPC-6012 TYPE 3 CLASS 2" at 11634.09,3332.96 h60
  text "OTHER +/-" at 11634.07,3176.96 h60
  text "BOW & TWIST:" at 10607.84,3019.96 h60
  text "X" at 11447.15,3019.96 h60
  text "ANSI IPC-6012 TYPE 3 CLASS 2" at 11634.09,3019.96 h60
  text "OTHER +/-" at 11634.07,2861.45 h60
  text "COPPER THICKNESS (FINISHED):" at 10533.07,2725.96 h60
  text "1.4MIL (1oz)" at 11413.07,2573.25 h60
  text "2MIL (1.4oz)" at 12180.07,2573.25 h60
  text "2.8MIL (2oz)" at 12907.07,2573.25 h60
  text "OUTER:" at 10890.07,2568.96 h60
  text "X" at 11284.61,2568.32 h60
  text "1.4MIL (1oz)" at 11413.07,2416.25 h60
  text "2.8MIL (2oz)" at 12180.07,2416.25 h60
  text "N/A" at 12906.61,2416.61 h60
  text "INNER SIGNAL:" at 10600.99,2411.96 h60
  text "X" at 11286.04,2411.96 h60
  text "DRILLING:" at 10533.07,2272.96 h60
  text "REFERENCE:" at 10607.84,2155.96 h60
  text "X" at 11256.07,2155.96 h60
  text "AS SHOWN" at 11443.07,2155.96 h60
  text "X" at 12157.07,2155.96 h60
  text "NC_DRILL FILES" at 12294.07,2155.96 h60
  text "PTH MIN COPPER THICKNESS:" at 10607.84,1997.96 h60
  text "X" at 11958.07,1997.96 h60
  text "1MIL" at 12095.07,1997.96 h60
  text "OTHER" at 12592.07,1997.96 h60
  text "BOARD FINISH:" at 10533.07,1838.96 h60
  text "SILKSCREEN:" at 10688.3,1720.96 h60
  text "X" at 11637.07,1720.96 h60
  text "TOP" at 11763.07,1720.96 h60
  text "X" at 12147.07,1720.96 h60
  text "BOTTOM" at 12274.07,1720.96 h60
  text "SILKSCREEN COLOR:" at 10688.3,1553.96 h60
  text "X" at 11636.03,1553.96 h60
  text "WHITE" at 11763.07,1553.96 h60
  text "OTHER" at 12274.07,1553.96 h60
  text "SOLDER RESIST COLOR:" at 10688.3,1383.96 h60
  text "X" at 11256.04,1224.77 h60
  text "GREEN" at 11383.07,1224.77 h60
  text "BLUE" at 11974.07,1224.77 h60
  text "OTHER" at 12512.07,1224.77 h60
  text "IMMERSION GOLD (ENIG)" at 11594.07,1036.25 h60
  text "ENEPIG" at 12931.61,1032.96 h60
  text "SURFACE FINISH:" at 10533.07,1031.96 h60
  text "IMM. TIN/SILVER OR EQUIV" at 10862.61,874.96 h60
  text "OTHER" at 12294.07,874.96 h60
  text "X" at 10687.61,870.32 h60
  text "ARRAY/PANEL:" at 10533.07,695.96 h60
  text "CUT AND TRIM PER MECH LAYER 1" at 11594.07,691.68 h60
  text "N.C. ROUTE" at 11594.07,539.96 h60
  text "V. SCORE" at 12460.07,539.96 h60
  text "CERTIFICATION:" at 10533.07,402.96 h60
  text "MATERIALS AND WORKMANSHIP FOR ALL PCBS" at 11258.07,402.96 h60
  text "TO MEET OR EXCEED THE REQUIREMENTS OF:" at 11258.07,304.96 h60
  text "X" at 10884.58,168.46 h60
  text "ANSI IPC-A-600F CLASS ->" at 11023.58,168.46 h60
  text "X" at 12662.63,168.46 h60
  text "2" at 12781.58,168.46 h60
  text "1" at 12466.58,166.96 h60
  text "3" at 13135.58,166.96 h60
  text "X" at 10886.63,8.96 h60
  text "UL 94V-0" at 11023.58,8.96 h60
  text "X" at 11698.63,8.96 h60
  text "RoHS" at 11835.58,8.96 h60
  text "OTHER" at 12479.98,8.96 h60
  text "PER ORDER" at 12877.04,8.96 h60
  text "ADDITIONAL REQUIREMENTS:" at 10533.07,-132.04 h60
  text "MICROSECTION:" at 10607.84,-247.04 h60
  text "YES" at 11513.58,-247.04 h60
  text "X" at 11797.61,-399.68 h60
  text "REQUIRED" at 12375.07,-403.18 h60
  text "BARE BOARD ELEC. TEST:" at 10607.84,-406.04 h60
  text "NONE" at 11913.58,-406.04 h60
  text "PER ORDER" at 12967.07,-406.04 h60
  text "Note: This board is 50 Ohms Controlled impedance and 16.5 mils trace thickness." at 2606.11,-527.18 h100
  text "MANUFACTURER'S UL:" at 10607.84,-563.04 h60
  text "RAIL" at 11773.58,-567.32 h60
  text "METAL" at 12265.39,-567.32 h60
  text "X" at 12640.61,-567.68 h60
  text "SILK" at 12777.07,-567.32 h60
  text ".Layer_Name" at -222.39,-2376.17 h60
M11 Gerber Information:
  lines w10: -1091.39,-2447.84 5508.61,-2447.84 ; -1091.39,-2244.51 5510.61,-2244.51 ; -1091.39,-2041.18 -1091.39,-2651.18 2913.61,-2651.18 5510.61,-2651.18 5510.61,-2041.18 -1090.89,-2041.18 -1090.89,-2651.18 484.61,-2651.18 ; 1373.61,-2651.18 1373.61,-2041.18 ; 2640.61,-2244.51 2640.61,-2041.18 ; 3480.61,-2244.51 3480.61,-2041.18 ; 4102.61,-2657.68 4102.61,-2454.84
  text "ALL ARTWORK VIEWED FROM TOP SIDE" at -1027.89,-2173.34 h60
  text "BOARD #:" at 1448.61,-2173.34 h60
  text ".PRJ_Number" at 1994.11,-2173.34 h60
  text "REV:" at 2838.61,-2173.34 h60
  text ".PCB_Rev" at 3130.11,-2173.34 h60
  text "SVN REV:" at 3676.61,-2173.34 h60
  text ".VersionControl_RevNumber" at 4182.61,-2173.34 h60
  text "LAYER NAME =" at -1027.89,-2376.17 h60
  text "PLOT NAME =" at -1027.89,-2582.01 h60
  text ".plot_File_Name" at -222.39,-2582.01 h60
  text "GENERATED    :" at 1450.61,-2582.01 h60
  text ".Print_Date" at 2320.11,-2582.01 h60
  text ".Print_Time" at 3049.11,-2582.01 h60
  text "TEXAS INSTRUMENTS" at 4313.61,-2582.01 h60
M12 Stackup:
  lines w5: 10527.61,6218.42 13395.61,6218.42 ; 10527.61,6313.62 13395.61,6313.62 ; 10467.61,5437.32 ccw(c10498.61,5437.32) 10498.61,5406.32 13424.61,5406.32 ccw(c13424.61,5437.32) 13455.61,5437.32 13455.61,6387.32 ccw(c13424.61,6387.32) 13424.61,6418.32 10498.61,6418.32 ccw(c10498.61,6387.32) 10467.61,6387.32 10467.61,5437.32
  text "Layer Stack Up Detail for: THS4541A DGN_HD_EVM.PcbDoc" at 10527.61,6336.47 h40
  text "Layer" at 10527.61,6278.12 h22
  text "Gerber" at 11139.44,6278.12 h22
  text "Copper" at 11451.44,6278.12 h22
  text "Dielectric" at 11799.35,6278.12 h22
  text "Dielectric" at 12162.66,6278.12 h22
  text "Dielectric" at 12619.54,6278.12 h22
  text "Dielectric" at 12982.85,6278.12 h22
  text "Name" at 10527.61,6234.12 h22
  text "Document" at 11139.44,6234.12 h22
  text "Thickness" at 11451.44,6234.12 h22
  text "Height" at 11799.35,6234.12 h22
  text "Material" at 12162.66,6234.12 h22
  text "Constant" at 12619.54,6234.12 h22
  text "Type" at 12982.85,6234.12 h22
  text "Top Solder Mask" at 10527.61,6171.65 h31
  text "(.GTS)" at 11139.44,6171.65 h31
  text "0.4mil" at 11799.35,6171.65 h31
  text "Solder Resist" at 12162.66,6171.65 h31
  text "3.50" at 12619.54,6171.65 h31
  text "Top Layer L1" at 10527.61,6083.1 h31
  text "(.GTL)" at 11139.44,6083.1 h31
  text "1.35mil" at 11451.44,6083.1 h31
  text "4.80" at 12631.61,6047.32 h31
  text "10mil" at 11799.35,6046.17 h31
  text "FR406" at 12162.66,6046.17 h31
  text "PrePreg" at 12982.85,6046.17 h31
  text "Layer 2 GND L2" at 10527.61,5994.55 h31
  text "(.GP1)" at 11139.44,5994.55 h31
  text "1.35mil" at 11451.44,5994.55 h31
  text "3.66" at 12633.61,5961.32 h31
  text "35.6mil" at 11799.35,5958.82 h31
  text "Rogers RO4350" at 12162.66,5958.82 h31
  text "Core" at 12982.85,5958.82 h31
  text "Layer 3 Power L3" at 10527.61,5906 h31
  text "(.GP2)" at 11139.44,5906 h31
  text "1.35mil" at 11451.44,5906 h31
  text "10mil" at 11799.35,5870.27 h31
  text "FR406" at 12162.66,5870.27 h31
  text "4.80" at 12633.61,5870.32 h31
  text "PrePreg" at 12982.85,5870.27 h31
  text "1.35mil" at 11459.61,5832.32 h31
  text "(.GBL)" at 11137.61,5828.32 h31
  text "Bottom Layer GND L4" at 10521.61,5818.32 h31
  text "3.50" at 12631.61,5753.32 h31
  text "Solder Resist" at 12157.61,5737.32 h31
  text "(.GBS)" at 11140.61,5734.32 h31
  text "0.4mil" at 11798.61,5730.32 h31
  text "Bottom Solder Mask" at 10521.61,5723.32 h31
  text ".Layer_Name" at -222.39,-2376.17 h60
M13 Component Bodies Top:
  text ".Layer_Name" at -222.39,-2376.17 h60
M14 Component Bodies Bottom:
  text ".Layer_Name" at -222.39,-2376.17 h60
M15 Courtyards Top:
  text ".Layer_Name" at -222.39,-2376.17 h60
M16 Courtyards Bottom:
  text ".Layer_Name" at -222.39,-2376.17 h60
Drill Drawing:
  text ".Layer_Name" at -222.39,-2376.17 h60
